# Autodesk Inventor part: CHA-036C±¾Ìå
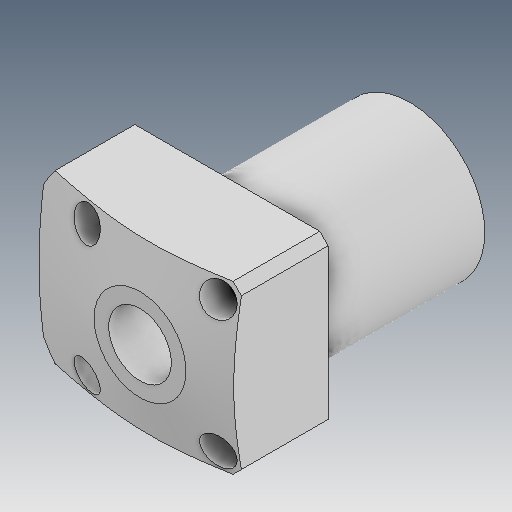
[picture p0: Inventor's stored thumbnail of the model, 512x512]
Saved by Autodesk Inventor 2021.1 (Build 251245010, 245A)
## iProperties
Created: 2019-12
Part Number: CHA-036C±¾Ìå
Material: Ogólny
Document SubType Name: Modeling
Designer: user
Density: 1 g/cm^3
Appearance: Domyślna
Author: user
Revision Number: ÈÎºÎ
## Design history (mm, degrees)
feature "NONE"
node "Bryła1"
